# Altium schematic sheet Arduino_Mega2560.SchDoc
size A4; DocumentNumber: 1; SheetNumber: 1; SheetTotal: 4
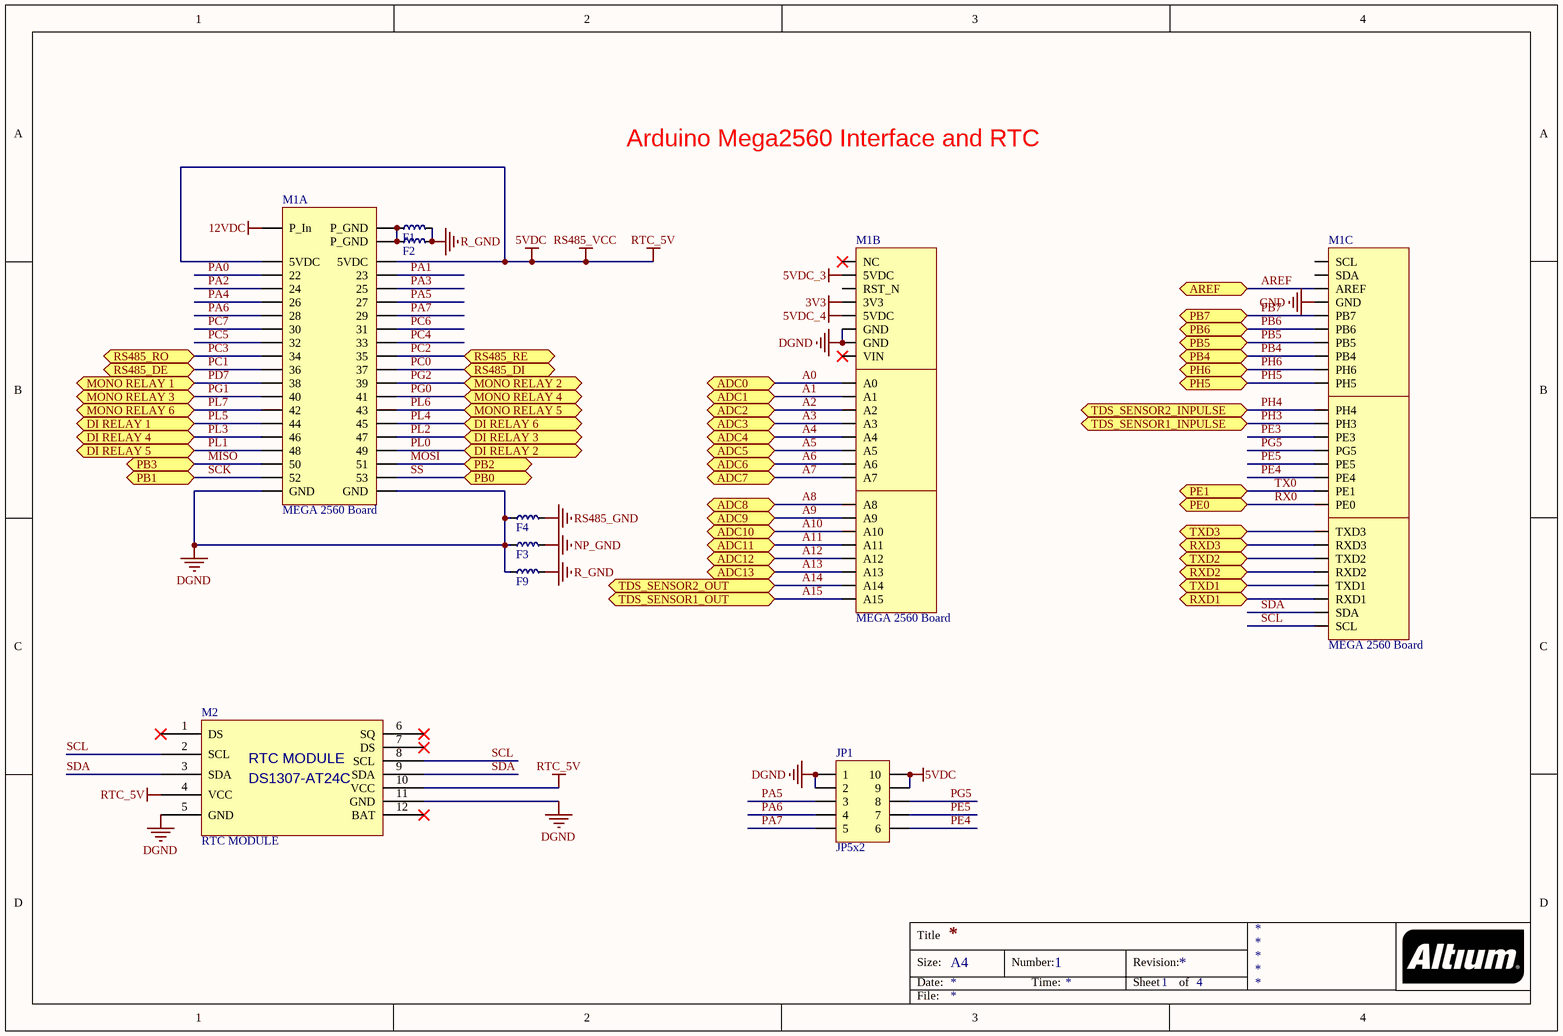
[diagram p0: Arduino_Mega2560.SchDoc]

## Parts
F1  FBFB0805  [RESC_0603]  (value not drawn)
F2  FBFB0805  [RESC_0603]  (value not drawn)
F3  FBFB0805  [RESC_0603]  (value not drawn)
F4  FBFB0805  [RESC_0603]  (value not drawn)
F9  FBFB0805  [RESC_0603]  (value not drawn)
JP1  JP5x2  [JP5-D2T]
M1  MEGA 2560 Board  [MEGA 2560]  (parts A,B,C of 3)
M2  RTC MODULE  [MODULE RTC DS1307-AT24C]

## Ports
ADC0, ADC1, ADC2, ADC3, ADC4, ADC5, ADC6, ADC7, ADC8, ADC9, ADC10, ADC11, ADC12, ADC13, AREF, DI RELAY 1, DI RELAY 2, DI RELAY 3, DI RELAY 4, DI RELAY 5, DI RELAY 6, MONO RELAY 1, MONO RELAY 2, MONO RELAY 3, MONO RELAY 4, MONO RELAY 5, MONO RELAY 6, PB0, PB1, PB2, PB3, PB4, PB5, PB6, PB7, PE0, PE1, PH5, PH6, RS485_DE, RS485_DI, RS485_RE, RS485_RO, RXD1, RXD2, RXD3, TDS_SENSOR1_INPULSE, TDS_SENSOR1_OUT, TDS_SENSOR2_INPULSE, TDS_SENSOR2_OUT, TXD1, TXD2, TXD3

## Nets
3V3: M1.3V1(3V3)
5VDC: JP1.9 JP1.10 M1.5V1(5VDC) M1.5V2(5VDC) M2.4(VCC) M2.10(VCC)  [also labelled RS485_VCC, RTC_5V]
5VDC_3: M1.5V3(5VDC)
5VDC_4: M1.5V4(5VDC)
12VDC: M1.P_In
DGND: F3.1 F4.1 F9.1 JP1.1 JP1.2 M1.G1(GND) M1.G2(GND) M1.G3(GND) M1.G4(GND) M2.5(GND) M2.11(GND)
GND: M1.G5(GND)
NP_GND: F3.2
R_GND: F1.2 F2.2 F9.2
RS485_GND: F4.2
A0: M1.A0 ; port ADC0
A1: M1.A1 ; port ADC1
A2: M1.A2 ; port ADC2
A3: M1.A3 ; port ADC3
A4: M1.A4 ; port ADC4
A5: M1.A5 ; port ADC5
A6: M1.A6 ; port ADC6
A7: M1.A7 ; port ADC7
A8: M1.A8 ; port ADC8
A9: M1.A9 ; port ADC9
A10: M1.A10 ; port ADC10
A11: M1.A11 ; port ADC11
A12: M1.A12 ; port ADC12
A13: M1.A13 ; port ADC13
A14: M1.A14 ; port TDS_SENSOR2_OUT
A15: M1.A15 ; port TDS_SENSOR1_OUT
AREF: M1.AREF ; port AREF
MISO: M1.50 ; port PB3
MOSI: M1.51 ; port PB2
PA0: M1.22
PA1: M1.23
PA2: M1.24
PA3: M1.25
PA4: M1.26
PA5: JP1.3 M1.27
PA6: JP1.4 M1.28
PA7: JP1.5 M1.29
PB4: M1.10(PB4) ; port PB4
PB5: M1.11(PB5) ; port PB5
PB6: M1.12(PB6) ; port PB6
PB7: M1.13(PB7) ; port PB7
PC0: M1.37 ; port RS485_DI
PC1: M1.36 ; port RS485_DE
PC2: M1.35 ; port RS485_RE
PC3: M1.34 ; port RS485_RO
PC4: M1.33
PC5: M1.32
PC6: M1.31
PC7: M1.30
PD7: M1.38 ; port MONO RELAY 1
PE3: M1.5(PE3)
PE4: JP1.6 M1.2(PE4)
PE5: JP1.7 M1.3(PE5)
PG0: M1.41 ; port MONO RELAY 4
PG1: M1.40 ; port MONO RELAY 3
PG2: M1.39 ; port MONO RELAY 2
PG5: JP1.8 M1.4(PG5)
PH3: M1.6(PH3) ; port TDS_SENSOR1_INPULSE
PH4: M1.7(PH4) ; port TDS_SENSOR2_INPULSE
PH5: M1.8(PH5) ; port PH5
PH6: M1.9(PH6) ; port PH6
PL0: M1.49 ; port DI RELAY 2
PL1: M1.48 ; port DI RELAY 5
PL2: M1.47 ; port DI RELAY 3
PL3: M1.46 ; port DI RELAY 4
PL4: M1.45 ; port DI RELAY 6
PL5: M1.44 ; port DI RELAY 1
PL6: M1.43 ; port MONO RELAY 5
PL7: M1.42 ; port MONO RELAY 6
RX0: M1.0(PE0) ; port PE0
RXD1: M1.19(RXD1) ; port RXD1
RXD2: M1.17(RXD2) ; port RXD2
RXD3: M1.15(RXD3) ; port RXD3
SCK: M1.52 ; port PB1
SCL: M1.21(SCL) M2.2(SCL) M2.8(SCL)
SDA: M1.20(SDA) M2.3(SDA) M2.9(SDA)
SS: M1.53 ; port PB0
TX0: M1.1(PE1) ; port PE1
TXD1: M1.18(TXD1) ; port TXD1
TXD2: M1.16(TXD2) ; port TXD2
TXD3: M1.14(TXD3) ; port TXD3
NetF1_1: F1.1 F2.1 M1.PGND1(P_GND) M1.PGND2(P_GND)

Not connected (* = marked no-connect by the designer): M1 NC* RST(RST_N) SCL SDA VIN*; M2 1(DS)* 6(SQ)* 7(DS)* 12(BAT)*

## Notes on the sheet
- Arduino Mega2560 Interface and RTC

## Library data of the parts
F1-F4 F9 = FB0603_1000Ohm: FERRITE BEAD 1000 OHM 0603
JP1 = JP5x2: WR-PHD 2.54 mm Dual Socket Header; Manufacturer: W¨¹rth Elektronik eiSos GmbH; partNo: 61301021821; ComponentLink1 Description: Manufacturer; ComponentLink2 Description: Datasheet; NoPins: 10
M1 = MEGA 2560 Board: Arduino ATMEGA 2560
M2 = RTC DS1307-AR24C: RTC DS1307-AT24C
